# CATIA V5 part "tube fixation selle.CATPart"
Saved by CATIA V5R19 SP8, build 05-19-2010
Part number: tube fixation selle
Bounding box of the stored display mesh (mm): x -4 to 4, y -12 to 12, z -3.804 to 3.804
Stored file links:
  G:\EU_thinkMotion\CFAO_2010\SIL_groupe1\SIL_groupe1\A reprendre\scador\monocycle\tube fixation selle.CATPart
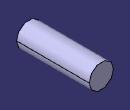
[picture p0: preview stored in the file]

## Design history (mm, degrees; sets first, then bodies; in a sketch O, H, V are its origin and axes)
Body1 (main body)
  Sketch1 on zx-plane, origin (0, 0, 0), H (-1, 0, 0), V (0, 0, 1)
    circle A1 centre (0, 0) radius 4
    radius A1 = 4
  Pad1: profile Sketch1, direction (0, 1, 0), length 12, opposite side length 12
